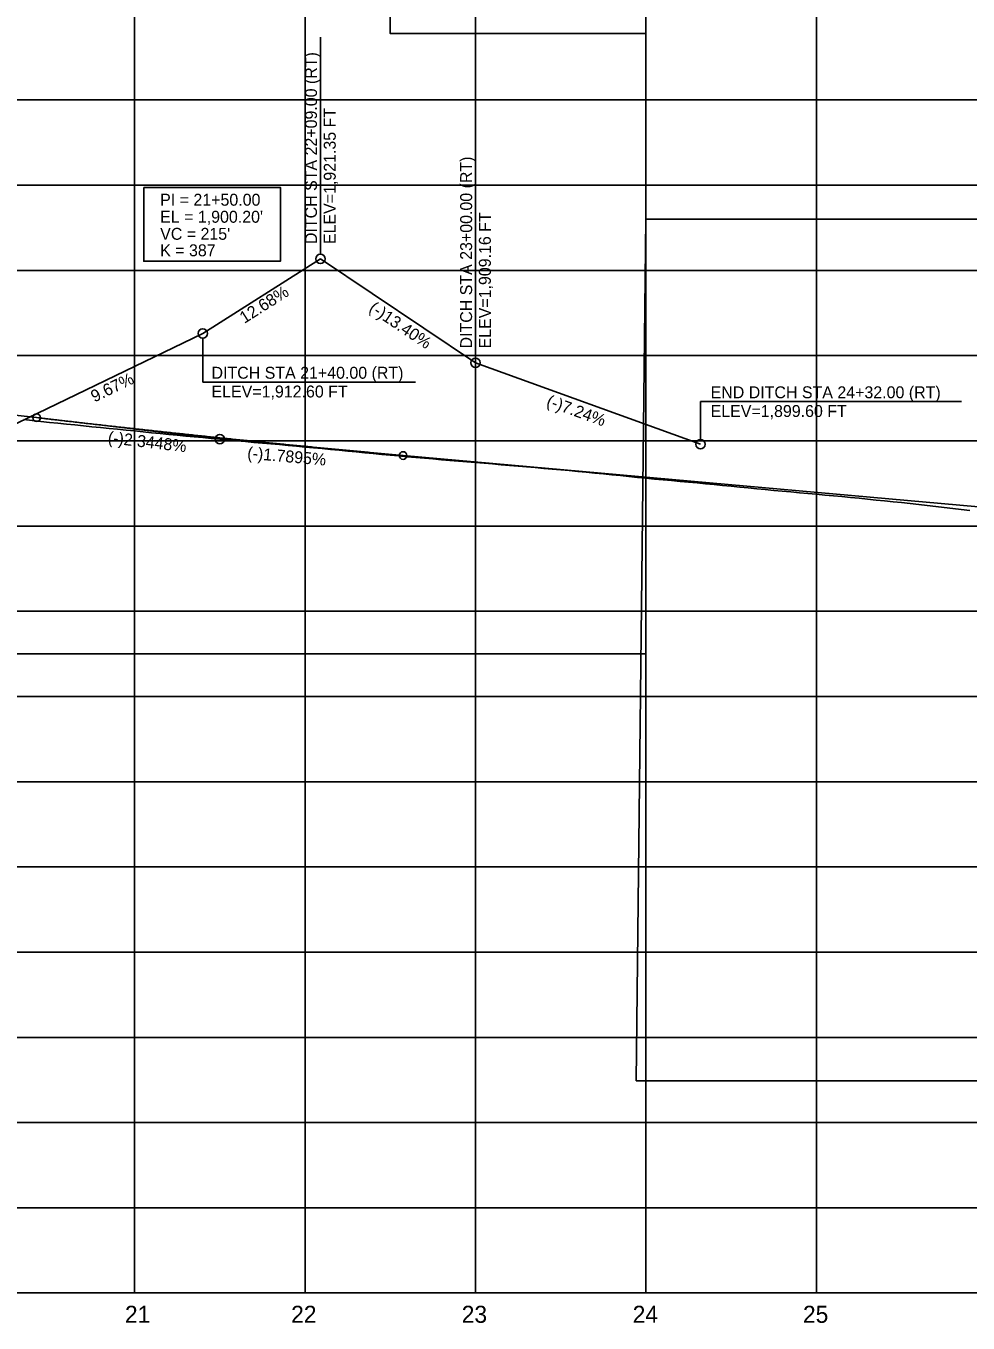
# Model space of a CAD drawing. Extents: x 553912 to 567693, y 512355 to 537539.
# Drawn here: x 558286 to 558838, y 513588 to 514349 of the extents above; entities that cross this region are included whole.
import ezdxf

# ---------------------------------------------------------------- set-up
doc = ezdxf.new("R2010")
doc.units = 0
for name, color, linetype in [('Exist Profile Cell', 7, 'Continuous'), ('Exist Vertical Profile Ground Line', 7, 'Continuous'), ('Exist Vertical Profile Horizontal Axis Label Major', 7, 'Continuous'), ('Prop Vertical Profile Curve Label', 7, 'Continuous'), ('Prop Vertical Profile Ditch Grade Right', 7, 'Continuous'), ('Prop Vertical Profile Ditch Grade Right Label', 7, 'Continuous'), ('Prop Vertical Profile Grade', 7, 'Continuous'), ('Prop Vertical Profile Grade Label', 7, 'Continuous'), ('Prop VPI Label', 7, 'Continuous'), ('Scratch_Level_5', 7, 'Continuous'), ('Sheet Profile Grid Major CELL', 7, 'Continuous')]:
    doc.layers.add(name, color=color, linetype=linetype)

msp = doc.modelspace()

# ---------------------------------------------------------------- linework, layer by layer
at = {"layer": 'Exist Profile Cell'}
msp.add_line((557249.45, 513605.4), (563849.45, 513605.4), dxfattribs=at)
msp.add_line((557249.45, 513605.4), (563849.45, 513605.4), dxfattribs=at)
at = {"layer": 'Exist Vertical Profile Ground Line'}
for points in [[(558284.45, 514117.98), (558289.45, 514117.4), (558294.45, 514116.82), (558299.45, 514116.24), (558304.45, 514115.73), (558309.45, 514115.22), (558314.45, 514114.7), (558319.45, 514114.19), (558324.45, 514113.68), (558329.45, 514113.17), (558334.45, 514112.69), (558339.45, 514112.18), (558344.45, 514111.68), (558349.45, 514111.17), (558354.45, 514110.67), (558359.45, 514110.17), (558364.45, 514109.66), (558369.45, 514109.17), (558374.45, 514108.67), (558379.45, 514108.19), (558384.45, 514107.72), (558389.45, 514107.25), (558394.45, 514106.77), (558399.45, 514106.3), (558404.45, 514105.84), (558409.45, 514105.37), (558414.45, 514104.92), (558419.45, 514104.48), (558424.45, 514104.03), (558429.45, 514103.59), (558434.45, 514103.15), (558439.45, 514102.7), (558444.45, 514102.2), (558449.45, 514101.76), (558454.45, 514101.29), (558459.45, 514100.81), (558464.45, 514100.33), (558469.45, 514099.85), (558474.45, 514099.37), (558479.45, 514098.89), (558484.45, 514098.36), (558489.45, 514097.88), (558494.45, 514097.4), (558499.45, 514096.97), (558504.45, 514096.53), (558509.45, 514096.09), (558514.45, 514095.66), (558519.45, 514095.22), (558524.45, 514094.77), (558529.45, 514094.33), (558534.45, 514093.92), (558539.45, 514093.5), (558544.45, 514093.07), (558549.45, 514092.65), (558554.45, 514092.23), (558559.45, 514091.81), (558564.45, 514091.4), (558569.45, 514090.98), (558574.45, 514090.54), (558579.45, 514090.11), (558584.45, 514089.67), (558589.45, 514089.23), (558594.45, 514088.79), (558599.45, 514088.35), (558604.45, 514087.91), (558609.45, 514087.47), (558614.45, 514086.98), (558619.45, 514086.47), (558624.45, 514085.97), (558629.45, 514085.46), (558634.45, 514084.96), (558639.45, 514084.45), (558644.45, 514083.95), (558649.45, 514083.45), (558654.45, 514082.98), (558659.45, 514082.52), (558664.45, 514082.05), (558669.45, 514081.58), (558674.45, 514081.12), (558679.45, 514080.65), (558684.45, 514080.18), (558689.45, 514079.69), (558694.45, 514079.22), (558699.45, 514078.74), (558704.45, 514078.27), (558709.45, 514077.79), (558714.45, 514077.32), (558719.45, 514076.82), (558724.45, 514076.34), (558729.45, 514075.87), (558734.45, 514075.41), (558739.45, 514074.94), (558744.45, 514074.48), (558749.45, 514074.02)], [(558284.45, 514117.98), (558289.45, 514117.4), (558294.45, 514116.82), (558299.45, 514116.24), (558304.45, 514115.73), (558309.45, 514115.22), (558314.45, 514114.7), (558319.45, 514114.19), (558324.45, 514113.68), (558329.45, 514113.17), (558334.45, 514112.69), (558339.45, 514112.18), (558344.45, 514111.68), (558349.45, 514111.17), (558354.45, 514110.67), (558359.45, 514110.17), (558364.45, 514109.66), (558369.45, 514109.17), (558374.45, 514108.67), (558379.45, 514108.19), (558384.45, 514107.72), (558389.45, 514107.25), (558394.45, 514106.77), (558399.45, 514106.3), (558404.45, 514105.84), (558409.45, 514105.37), (558414.45, 514104.92), (558419.45, 514104.48), (558424.45, 514104.03), (558429.45, 514103.59), (558434.45, 514103.15), (558439.45, 514102.7), (558444.45, 514102.2), (558449.45, 514101.76), (558454.45, 514101.29), (558459.45, 514100.81), (558464.45, 514100.33), (558469.45, 514099.85), (558474.45, 514099.37), (558479.45, 514098.89), (558484.45, 514098.36), (558489.45, 514097.88), (558494.45, 514097.4), (558499.45, 514096.97), (558504.45, 514096.53), (558509.45, 514096.09), (558514.45, 514095.66), (558519.45, 514095.22), (558524.45, 514094.77), (558529.45, 514094.33), (558534.45, 514093.92), (558539.45, 514093.5), (558544.45, 514093.07), (558549.45, 514092.65), (558554.45, 514092.23), (558559.45, 514091.81), (558564.45, 514091.4), (558569.45, 514090.98), (558574.45, 514090.54), (558579.45, 514090.11), (558584.45, 514089.67), (558589.45, 514089.23), (558594.45, 514088.79), (558599.45, 514088.35), (558604.45, 514087.91), (558609.45, 514087.47), (558614.45, 514086.98), (558619.45, 514086.47), (558624.45, 514085.97), (558629.45, 514085.46), (558634.45, 514084.96), (558639.45, 514084.45), (558644.45, 514083.95), (558649.45, 514083.45), (558654.45, 514082.98), (558659.45, 514082.52), (558664.45, 514082.05), (558669.45, 514081.58), (558674.45, 514081.12), (558679.45, 514080.65), (558684.45, 514080.18), (558689.45, 514079.69), (558694.45, 514079.22), (558699.45, 514078.74), (558704.45, 514078.27), (558709.45, 514077.79), (558714.45, 514077.32), (558719.45, 514076.82), (558724.45, 514076.34), (558729.45, 514075.87), (558734.45, 514075.41), (558739.45, 514074.94), (558744.45, 514074.48), (558749.45, 514074.02)], [(558749.45, 514074.02), (558754.45, 514073.55), (558759.45, 514073.1), (558764.45, 514072.64), (558769.45, 514072.15), (558774.45, 514071.66), (558779.45, 514071.16), (558784.45, 514070.66), (558789.45, 514070.16), (558794.45, 514069.67), (558799.45, 514069.16), (558804.45, 514068.66), (558809.45, 514068.08), (558814.45, 514067.48), (558819.45, 514066.89), (558824.45, 514066.29), (558829.45, 514065.69), (558834.45, 514065.1), (558839.45, 514064.48)], [(558749.45, 514074.02), (558754.45, 514073.55), (558759.45, 514073.1), (558764.45, 514072.64), (558769.45, 514072.15), (558774.45, 514071.66), (558779.45, 514071.16), (558784.45, 514070.66), (558789.45, 514070.16), (558794.45, 514069.67), (558799.45, 514069.16), (558804.45, 514068.66), (558809.45, 514068.08), (558814.45, 514067.48), (558819.45, 514066.89), (558824.45, 514066.29), (558829.45, 514065.69), (558834.45, 514065.1), (558839.45, 514064.48)]]:
    msp.add_lwpolyline(points, dxfattribs=at)
at = {"layer": 'Prop Vertical Profile Curve Label'}
for centre in [(558291.95, 514119), (558506.95, 514096.78)]:
    msp.add_circle(centre, 2.25, dxfattribs=at)
at = {"layer": 'Prop Vertical Profile Ditch Grade Right'}
for points in [[(558269.45, 514110.4), (558389.45, 514168.4), (558458.45, 514212.15)], [(558458.45, 514212.15), (558549.45, 514151.2), (558681.45, 514103.4)]]:
    msp.add_lwpolyline(points, dxfattribs=at)
at = {"layer": 'Prop Vertical Profile Ditch Grade Right Label'}
for p, q in [((558458.45, 514342.23), (558458.45, 514214.9)), ((558549.45, 514280.99), (558549.45, 514153.95)), ((558389.45, 514165.65), (558389.45, 514139.83)), ((558514.31, 514139.83), (558389.45, 514139.83)), ((558681.45, 514106.15), (558681.45, 514128.37)), ((558834.63, 514128.37), (558681.45, 514128.37))]:
    msp.add_line(p, q, dxfattribs=at)
for centre in [(558458.45, 514212.15), (558458.45, 514212.15), (558458.45, 514212.15), (558389.45, 514168.4), (558549.45, 514151.2), (558681.45, 514103.4)]:
    msp.add_circle(centre, 2.75, dxfattribs=at)
at = {"layer": 'Prop Vertical Profile Grade'}
for p, q in [((558279.45, 514120.47), (558291.95, 514119)), ((558506.95, 514096.78), (558844.45, 514066.58))]:
    msp.add_line(p, q, dxfattribs=at)
msp.add_spline([(558291.95, 514119), (558296.25, 514118.5), (558300.55, 514118), (558304.85, 514117.5), (558309.15, 514117.01), (558313.45, 514116.51), (558317.75, 514116.02), (558322.05, 514115.53), (558326.35, 514115.05), (558330.65, 514114.56), (558334.95, 514114.08), (558339.25, 514113.6), (558343.55, 514113.13), (558347.85, 514112.65), (558352.15, 514112.18), (558356.45, 514111.71), (558360.75, 514111.24), (558365.05, 514110.78), (558369.35, 514110.32), (558373.65, 514109.86), (558377.95, 514109.4), (558382.25, 514108.94), (558386.55, 514108.49), (558390.85, 514108.04), (558395.15, 514107.59), (558399.45, 514107.15), (558403.75, 514106.7), (558408.05, 514106.26), (558412.35, 514105.82), (558416.65, 514105.39), (558420.95, 514104.95), (558425.25, 514104.52), (558429.55, 514104.09), (558433.85, 514103.67), (558438.15, 514103.24), (558442.45, 514102.82), (558446.75, 514102.4), (558451.05, 514101.99), (558455.35, 514101.57), (558459.65, 514101.16), (558463.95, 514100.75), (558468.25, 514100.34), (558472.55, 514099.94), (558476.85, 514099.53), (558481.15, 514099.13), (558485.45, 514098.74), (558489.75, 514098.34), (558494.05, 514097.95), (558498.35, 514097.56), (558502.65, 514097.17), (558506.95, 514096.78)], degree=3, dxfattribs=at)
at = {"layer": 'Prop VPI Label'}
for p, q in [((558291.95, 514119), (558396.72, 514106.72)), ((558506.95, 514096.78), (558402.19, 514106.16))]:
    msp.add_line(p, q, dxfattribs=at)
msp.add_lwpolyline([(558354.86, 514254.1), (558435, 514254.1), (558435, 514210.74), (558354.86, 514210.74)], close=True, dxfattribs=at)
msp.add_circle((558399.45, 514106.4), 2.75, dxfattribs=at)
at = {"layer": 'Scratch_Level_5'}
for points in [[(557207.08, 514505.4), (557207.08, 513980.4), (558649.45, 513980.4), (558649.45, 514344.35), (558499.4, 514344.35), (558499.4, 514505.4)], [(558649.45, 514235.4), (558643.76, 513729.91), (560043.76, 513729.91), (560049.45, 514074.35), (559899.4, 514074.35), (559899.4, 514235.4)]]:
    msp.add_lwpolyline(points, close=True, dxfattribs=at)
at = {"layer": 'Sheet Profile Grid Major CELL'}
for p, q in [((558349.45, 513605.4), (558349.45, 514805.4)), ((558449.45, 513605.4), (558449.45, 514805.4)), ((558549.45, 513605.4), (558549.45, 514805.4)), ((558649.45, 513605.4), (558649.45, 514805.4)), ((558749.45, 513605.4), (558749.45, 514805.4)), ((563849.45, 514305.4), (557249.45, 514305.4)), ((563849.45, 514255.4), (557249.45, 514255.4)), ((563849.45, 514205.4), (557249.45, 514205.4)), ((563849.45, 514155.4), (557249.45, 514155.4)), ((563849.45, 514105.4), (557249.45, 514105.4)), ((563849.45, 514055.4), (557249.45, 514055.4)), ((563849.45, 514005.4), (557249.45, 514005.4)), ((563849.45, 513955.4), (557249.45, 513955.4)), ((563849.45, 513905.4), (557249.45, 513905.4)), ((563849.45, 513855.4), (557249.45, 513855.4)), ((563849.45, 513805.4), (557249.45, 513805.4)), ((563849.45, 513755.4), (557249.45, 513755.4)), ((563849.45, 513705.4), (557249.45, 513705.4)), ((563849.45, 513655.4), (557249.45, 513655.4))]:
    msp.add_line(p, q, dxfattribs=at)

# ---------------------------------------------------------------- texts
at = {"layer": 'Exist Vertical Profile Horizontal Axis Label Major'}
for s, p in [('21', (558343.79, 513587.9)), ('21', (558343.79, 513587.9)), ('22', (558441.28, 513587.9)), ('22', (558441.28, 513587.9)), ('23', (558541.37, 513587.9)), ('23', (558541.37, 513587.9)), ('24', (558641.66, 513587.9)), ('24', (558641.66, 513587.9)), ('25', (558741.56, 513587.9)), ('25', (558741.56, 513587.9))]:
    msp.add_text(s, height=10, dxfattribs=at).set_placement(p)
at = {"layer": 'Prop Vertical Profile Curve Label'}
for s, p in [("VC = 215'", (558364.45, 514223.35)), ('K = 387', (558364.45, 514213.68))]:
    msp.add_text(s, height=7, dxfattribs=at).set_placement(p)
at = {"layer": 'Prop Vertical Profile Ditch Grade Right'}
for s, p in [('DITCH STA 22+09.00 (RT)', (558456.45, 514220.82)), ('DITCH STA 23+00.00 (RT)', (558547.45, 514159.58))]:
    msp.add_text(s, height=7, rotation=90, dxfattribs=at).set_placement(p)
for s, p in [('DITCH STA 21+40.00 (RT)', (558394.57, 514141.83)), ('END DITCH STA 24+32.00 (RT)', (558687.38, 514130.37))]:
    msp.add_text(s, height=7, dxfattribs=at).set_placement(p)
at = {"layer": 'Prop Vertical Profile Ditch Grade Right Label'}
for s, rotation, p in [('ELEV=1,921.35 FT', 90, (558467.45, 514220.82)), ('ELEV=1,909.16 FT', 90, (558558.45, 514159.58)), ('12.68%', 32.37707, (558413.86, 514173.97)), ('(-)13.40%', 326.18661, (558486.42, 514181.81)), ('9.67%', 25.79603, (558325.87, 514127.84)), ('(-)7.24%', 340.0936, (558590.55, 514125.96))]:
    msp.add_text(s, height=7, rotation=rotation, dxfattribs=at).set_placement(p)
for s, p in [('ELEV=1,912.60 FT', (558394.57, 514130.83)), ('ELEV=1,899.60 FT', (558687.38, 514119.37))]:
    msp.add_text(s, height=7, dxfattribs=at).set_placement(p)
at = {"layer": 'Prop Vertical Profile Grade Label'}
for s, rotation, p in [('(-)2.3448%', 353.31309, (558333.49, 514104.07)), ('(-)1.7895%', 354.88715, (558415.35, 514094.94))]:
    msp.add_text(s, height=7, rotation=rotation, dxfattribs=at).set_placement(p)
at = {"layer": 'Prop VPI Label'}
for s, p in [('PI = 21+50.00', (558364.45, 514243.35)), ("EL = 1,900.20'", (558364.45, 514233.35))]:
    msp.add_text(s, height=7, dxfattribs=at).set_placement(p)

doc.saveas('drawing.dxf')
